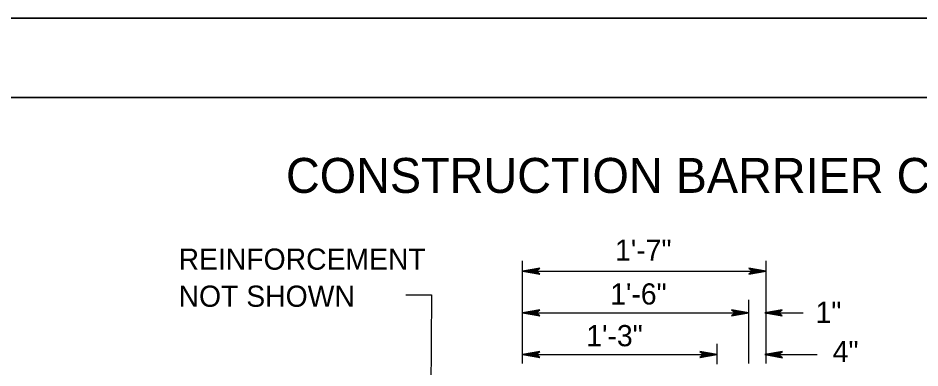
# Model space of a CAD drawing. Extents: x 499883 to 500983, y 499104 to 499764.
# Drawn here: x 500228.2 to 500398.4, y 499697.5 to 499763.6 of the extents above; entities that cross this region are included whole.
import ezdxf

# ---------------------------------------------------------------- set-up
doc = ezdxf.new("R2010")
doc.units = 0
for name, color, linetype in [('1', 7, 'Continuous'), ('24', 7, 'Continuous'), ('41', 7, 'Continuous'), ('5', 7, 'Continuous')]:
    doc.layers.add(name, color=color, linetype=linetype)

msp = doc.modelspace()

# ---------------------------------------------------------------- linework, layer by layer
at = {"layer": '1'}
for p, q in [((500982.94, 499763.64), (499934.77, 499763.64)), ((500979.94, 499748.64), (499989.94, 499748.64))]:
    msp.add_line(p, q, dxfattribs=at)
at = {"layer": '24'}
for points in [[(500323.42, 499715.83), (500326.69, 499715.25), (500325.91, 499715.83), (500326.68, 499716.4), (500323.42, 499715.83), (500323.64, 499715.83), (500326.6, 499715.29), (500325.85, 499715.83), (500326.55, 499716.35), (500323.76, 499715.84), (500323.86, 499715.83), (500326.4, 499715.37), (500325.83, 499715.83), (500326.42, 499716.28), (500323.91, 499715.82), (500324.02, 499715.84), (500326.24, 499715.44), (500325.81, 499715.82), (500326.25, 499716.22), (500324.34, 499715.84), (500324.52, 499715.84), (500326.08, 499715.52), (500325.78, 499715.82), (500326.1, 499716.14), (500324.56, 499715.83), (500324.73, 499715.82), (500325.9, 499715.61), (500325.68, 499715.84), (500325.92, 499716.07), (500324.89, 499715.83), (500325.06, 499715.81), (500325.76, 499715.67), (500325.64, 499715.83), (500325.84, 499716.01), (500325.14, 499715.82), (500325.6, 499715.72), (500325.53, 499715.84), (500325.74, 499715.97), (500325.26, 499715.84), (500325.56, 499715.77), (500325.43, 499715.87), (500325.58, 499715.92), (500325.43, 499715.83), (500325.51, 499715.82)], [(500369.39, 499715.83), (500366.11, 499716.4), (500366.89, 499715.83), (500366.13, 499715.26), (500369.39, 499715.83), (500369.17, 499715.82), (500366.2, 499716.36), (500366.96, 499715.82), (500366.26, 499715.3), (500369.05, 499715.81), (500368.94, 499715.83), (500366.4, 499716.28), (500366.97, 499715.82), (500366.39, 499715.37), (500368.89, 499715.83), (500368.78, 499715.81), (500366.56, 499716.21), (500367, 499715.83), (500366.55, 499715.43), (500368.47, 499715.81), (500368.28, 499715.81), (500366.73, 499716.13), (500367.03, 499715.83), (500366.7, 499715.51), (500368.25, 499715.83), (500368.07, 499715.84), (500366.91, 499716.04), (500367.13, 499715.81), (500366.89, 499715.58), (500367.91, 499715.83), (500367.75, 499715.84), (500367.05, 499715.98), (500367.16, 499715.82), (500366.97, 499715.64), (500367.66, 499715.83), (500367.21, 499715.93), (500367.27, 499715.81), (500367.07, 499715.68), (500367.55, 499715.81), (500367.25, 499715.88), (500367.37, 499715.79), (500367.23, 499715.73), (500367.37, 499715.82), (500367.3, 499715.83)], [(500323.42, 499707.95), (500326.69, 499707.37), (500325.91, 499707.95), (500326.68, 499708.52), (500323.42, 499707.95), (500323.64, 499707.96), (500326.6, 499707.42), (500325.85, 499707.96), (500326.55, 499708.48), (500323.76, 499707.97), (500323.86, 499707.95), (500326.4, 499707.5), (500325.83, 499707.96), (500326.42, 499708.4), (500323.91, 499707.95), (500324.02, 499707.97), (500326.24, 499707.57), (500325.81, 499707.95), (500326.25, 499708.35), (500324.34, 499707.97), (500324.52, 499707.97), (500326.08, 499707.65), (500325.78, 499707.94), (500326.1, 499708.27), (500324.56, 499707.95), (500324.73, 499707.94), (500325.9, 499707.74), (500325.68, 499707.97), (500325.92, 499708.19), (500324.89, 499707.95), (500325.06, 499707.93), (500325.76, 499707.8), (500325.64, 499707.96), (500325.84, 499708.13), (500325.14, 499707.95), (500325.6, 499707.84), (500325.53, 499707.97), (500325.74, 499708.09), (500325.26, 499707.97), (500325.56, 499707.89), (500325.43, 499707.99), (500325.58, 499708.05), (500325.43, 499707.96), (500325.51, 499707.94)], [(500366.14, 499707.95), (500362.87, 499708.53), (500363.65, 499707.95), (500362.88, 499707.38), (500366.14, 499707.95), (500365.92, 499707.95), (500362.96, 499708.49), (500363.71, 499707.94), (500363.02, 499707.43), (500365.81, 499707.94), (500365.7, 499707.95), (500363.16, 499708.4), (500363.73, 499707.94), (500363.14, 499707.5), (500365.65, 499707.95), (500365.54, 499707.94), (500363.32, 499708.34), (500363.75, 499707.95), (500363.31, 499707.55), (500365.22, 499707.93), (500365.04, 499707.94), (500363.48, 499708.25), (500363.79, 499707.96), (500363.46, 499707.64), (500365, 499707.95), (500364.83, 499707.96), (500363.66, 499708.16), (500363.89, 499707.93), (500363.64, 499707.71), (500364.67, 499707.95), (500364.5, 499707.97), (500363.8, 499708.1), (500363.92, 499707.94), (500363.73, 499707.77), (500364.42, 499707.95), (500363.96, 499708.06), (500364.03, 499707.94), (500363.83, 499707.81), (500364.3, 499707.93), (500364, 499708.01), (500364.13, 499707.91), (500363.98, 499707.85), (500364.13, 499707.94), (500364.05, 499707.96)], [(500369.14, 499707.95), (500372.41, 499707.37), (500371.63, 499707.95), (500372.4, 499708.52), (500369.14, 499707.95), (500369.36, 499707.96), (500372.32, 499707.42), (500371.57, 499707.96), (500372.26, 499708.48), (500369.47, 499707.97), (500369.58, 499707.95), (500372.12, 499707.5), (500371.55, 499707.96), (500372.14, 499708.4), (500369.63, 499707.95), (500369.74, 499707.97), (500371.96, 499707.57), (500371.53, 499707.95), (500371.97, 499708.35), (500370.06, 499707.97), (500370.24, 499707.97), (500371.8, 499707.65), (500371.49, 499707.94), (500371.82, 499708.27), (500370.27, 499707.95), (500370.45, 499707.94), (500371.62, 499707.74), (500371.39, 499707.97), (500371.64, 499708.19), (500370.61, 499707.95), (500370.78, 499707.93), (500371.48, 499707.8), (500371.36, 499707.96), (500371.55, 499708.13), (500370.86, 499707.95), (500371.32, 499707.84), (500371.25, 499707.97), (500371.45, 499708.09), (500370.98, 499707.97), (500371.28, 499707.89), (500371.15, 499707.99), (500371.29, 499708.05), (500371.15, 499707.96), (500371.23, 499707.94)], [(500323.42, 499700.08), (500326.69, 499699.5), (500325.91, 499700.08), (500326.68, 499700.65), (500323.42, 499700.08), (500323.64, 499700.08), (500326.6, 499699.54), (500325.85, 499700.08), (500326.55, 499700.6), (500323.76, 499700.09), (500323.86, 499700.08), (500326.4, 499699.63), (500325.83, 499700.08), (500326.42, 499700.53), (500323.91, 499700.08), (500324.02, 499700.09), (500326.24, 499699.69), (500325.81, 499700.08), (500326.25, 499700.48), (500324.34, 499700.09), (500324.52, 499700.09), (500326.08, 499699.78), (500325.78, 499700.07), (500326.1, 499700.39), (500324.56, 499700.08), (500324.73, 499700.07), (500325.9, 499699.87), (500325.68, 499700.09), (500325.92, 499700.32), (500324.89, 499700.08), (500325.06, 499700.06), (500325.76, 499699.93), (500325.64, 499700.08), (500325.84, 499700.26), (500325.14, 499700.08), (500325.6, 499699.97), (500325.53, 499700.09), (500325.74, 499700.22), (500325.26, 499700.09), (500325.56, 499700.02), (500325.43, 499700.12), (500325.58, 499700.18), (500325.43, 499700.08), (500325.51, 499700.07)], [(500360.15, 499700.08), (500356.87, 499700.66), (500357.65, 499700.08), (500356.89, 499699.51), (500360.15, 499700.08), (500359.93, 499700.07), (500356.96, 499700.61), (500357.71, 499700.07), (500357.02, 499699.55), (500359.81, 499700.06), (500359.7, 499700.08), (500357.16, 499700.53), (500357.73, 499700.07), (500357.15, 499699.63), (500359.65, 499700.08), (500359.54, 499700.06), (500357.32, 499700.46), (500357.75, 499700.08), (500357.31, 499699.68), (500359.23, 499700.06), (500359.04, 499700.06), (500357.49, 499700.38), (500357.79, 499700.09), (500357.46, 499699.76), (500359.01, 499700.08), (500358.83, 499700.09), (500357.67, 499700.29), (500357.89, 499700.06), (500357.65, 499699.84), (500358.67, 499700.08), (500358.51, 499700.09), (500357.81, 499700.23), (500357.92, 499700.07), (500357.73, 499699.9), (500358.42, 499700.08), (500357.97, 499700.19), (500358.03, 499700.06), (500357.83, 499699.94), (500358.31, 499700.06), (500358.01, 499700.14), (500358.13, 499700.04), (500357.99, 499699.98), (500358.13, 499700.07), (500358.06, 499700.09)]]:
    msp.add_lwpolyline(points, dxfattribs=at)
at = {"layer": '41'}
for points in [[(499934.77, 499763.64), (500982.94, 499763.64), (500982.94, 499103.64), (499934.77, 499103.64)], [(499989.94, 499748.64), (500979.94, 499748.64), (500979.94, 499118.64), (499989.94, 499118.64)]]:
    msp.add_lwpolyline(points, close=True, dxfattribs=at)
at = {"layer": '5'}
for p, q in [((500323.42, 499698.41), (500323.42, 499717.8)), ((500369.39, 499698.41), (500369.39, 499717.8)), ((500323.42, 499715.83), (500369.39, 499715.83)), ((500366.14, 499698.41), (500366.14, 499710.43)), ((500323.42, 499707.95), (500366.14, 499707.95)), ((500369.14, 499707.95), (500376.37, 499707.95)), ((500360.15, 499698.27), (500360.15, 499702.08)), ((500323.42, 499700.08), (500360.15, 499700.08)), ((500369.14, 499700.08), (500379, 499700.08))]:
    msp.add_line(p, q, dxfattribs=at)
for points in [[(500301.41, 499711.38), (500306.23, 499711.38), (500306.12, 499693.22)], [(500369.14, 499700.08), (500372.46, 499699.49), (500371.67, 499700.08), (500372.45, 499700.66), (500369.14, 499700.08), (500369.36, 499700.08), (500372.37, 499699.53), (500371.61, 499700.08), (500372.31, 499700.61), (500369.48, 499700.09), (500369.59, 499700.08), (500372.17, 499699.62), (500371.59, 499700.08), (500372.18, 499700.54), (500369.64, 499700.08), (500369.75, 499700.09), (500372, 499699.69), (500371.57, 499700.08), (500372.01, 499700.48), (500370.07, 499700.09), (500370.26, 499700.09), (500371.84, 499699.77), (500371.53, 499700.07), (500371.86, 499700.4), (500370.29, 499700.08), (500370.47, 499700.07), (500371.66, 499699.86), (500371.43, 499700.09), (500371.67, 499700.32), (500370.63, 499700.08), (500370.8, 499700.06), (500371.51, 499699.92), (500371.4, 499700.08), (500371.59, 499700.26), (500370.89, 499700.08), (500371.35, 499699.97), (500371.28, 499700.09), (500371.49, 499700.22), (500371, 499700.09), (500371.31, 499700.02), (500371.18, 499700.12), (500371.33, 499700.18), (500371.18, 499700.08), (500371.26, 499700.07)]]:
    msp.add_lwpolyline(points, dxfattribs=at)

# ---------------------------------------------------------------- texts
for s, height, p in [('CONSTRUCTION BARRIER CURB CONNECTION DETAILS', 6.6001, (500278.77, 499730.61)), ('1\'-7"', 4, (500340.88, 499717.8)), ('REINFORCEMENT', 4, (500258.5, 499716.1)), ('NOT SHOWN', 4, (500258.5, 499709.1)), ('1\'-6"', 4, (500339.96, 499709.53)), ('1"', 4, (500378.71, 499706.06)), ('1\'-3"', 4, (500335.45, 499701.65)), ('4"', 4, (500381.95, 499698.65))]:
    msp.add_text(s, height=height, dxfattribs=at).set_placement(p)

doc.saveas('drawing.dxf')
